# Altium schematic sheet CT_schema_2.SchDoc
size 316 x 185 mm
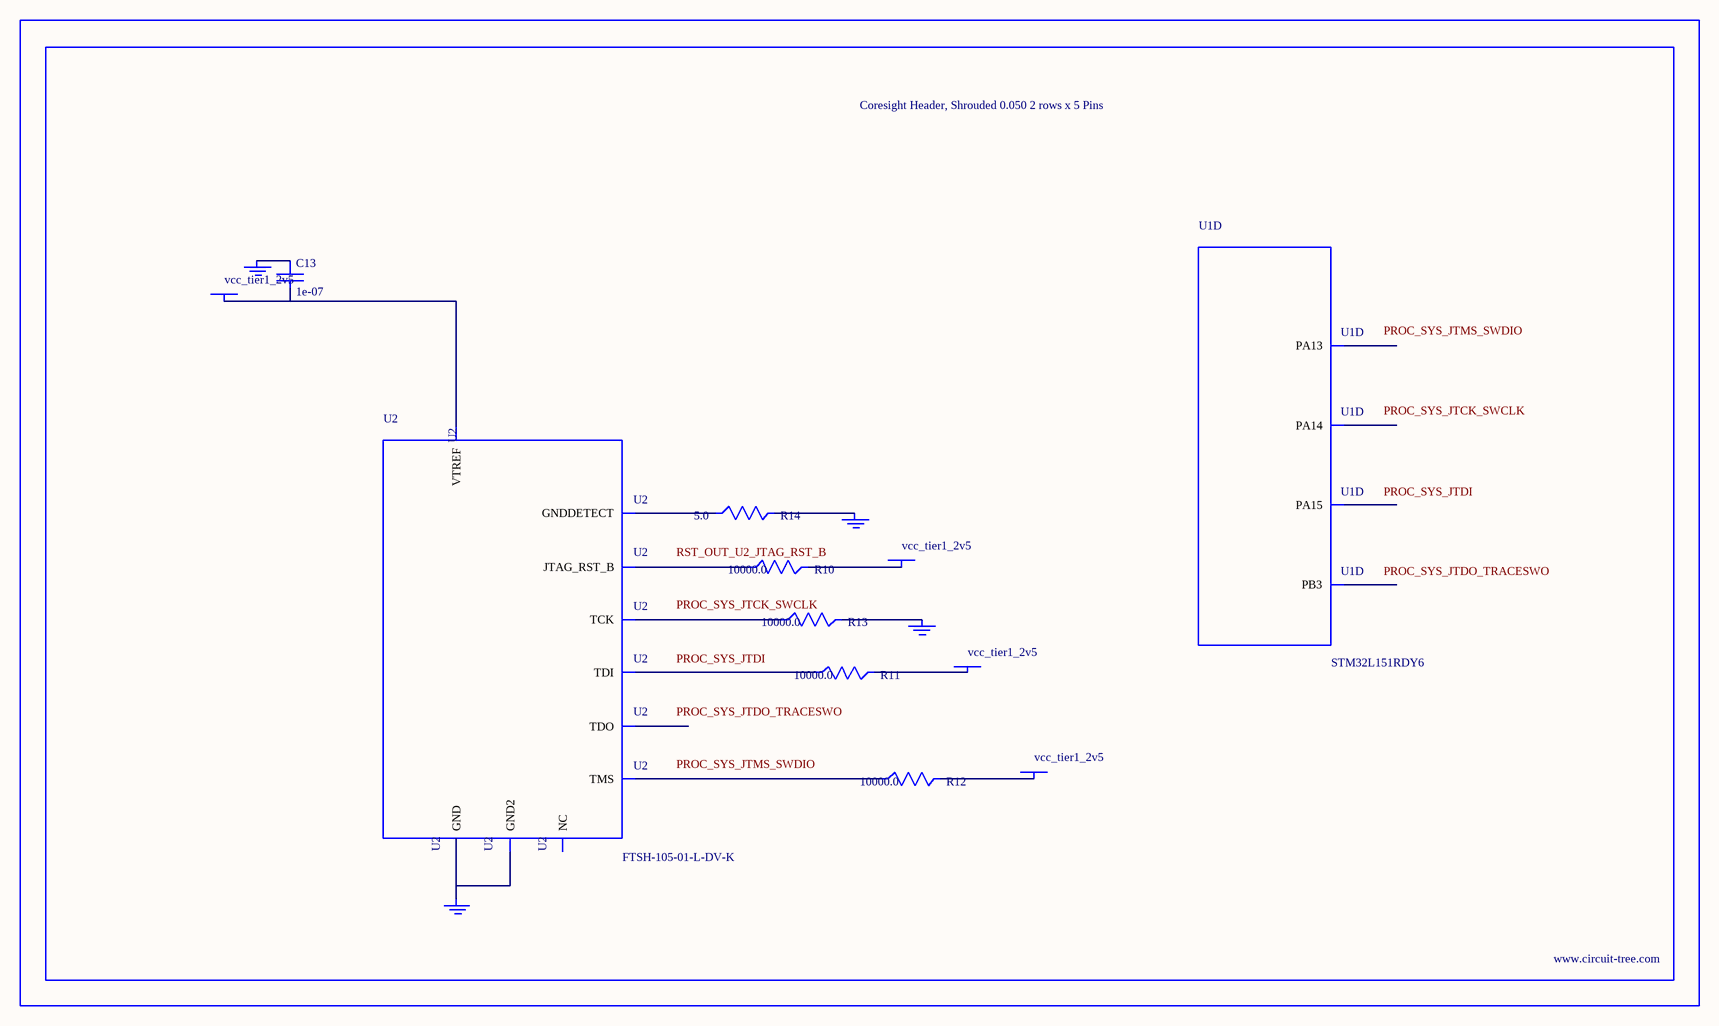
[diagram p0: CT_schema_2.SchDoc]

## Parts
BORDER1  (no value)
C13  1e-07  [C0402]
GND_INSTANCE_1_0  (no value)
GND_INSTANCE_1_1  (no value)
GND_INSTANCE_1_2  (no value)
GND_INSTANCE_1_3  (no value)
POWER_INSTANCE_1_0  vcc_tier1_2v5
POWER_INSTANCE_1_1  vcc_tier1_2v5
POWER_INSTANCE_1_2  vcc_tier1_2v5
POWER_INSTANCE_1_3  vcc_tier1_2v5
R10  10000.0  [R0603]
R11  10000.0  [R0603]
R12  10000.0  [R0603]
R13  10000.0  [R0603]
R14  5.0  [R0603]
U1  STM32L151RDY6  [WLCSP64]  (part D of 8)
U2  FTSH-105-01-L-DV-K  [SAMTEC_FTSH-105-01-L-DV-K]

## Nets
NetC13_1: C13.1 GND_INSTANCE_1_0.0(GND)
NetC13_2: C13.2 POWER_INSTANCE_1_0.0(PWR) U2.1(VTREF)
NetGND_INSTANCE_1_1_0: GND_INSTANCE_1_1.0(GND) R13.2
NetGND_INSTANCE_1_2_0: GND_INSTANCE_1_2.0(GND) R14.2
NetGND_INSTANCE_1_3_0: GND_INSTANCE_1_3.0(GND) U2.3(GND) U2.5(GND2)
NetPOWER_INSTANCE_1_1_0: POWER_INSTANCE_1_1.0(PWR) R12.2
NetPOWER_INSTANCE_1_2_0: POWER_INSTANCE_1_2.0(PWR) R11.2
NetPOWER_INSTANCE_1_3_0: POWER_INSTANCE_1_3.0(PWR) R10.2
NetR10_1: R10.1 U2.10(JTAG_RST_B)
NetR11_1: R11.1 U2.8(TDI)
NetR12_1: R12.1 U2.2(TMS)
NetR13_1: R13.1 U2.4(TCK)
NetR14_1: R14.1 U2.9(GNDDETECT)

Not connected (* = marked no-connect by the designer): U1 A4(PB3) B2(PA14) C3(PA15) D4(PA13); U2 6(TDO) 7(NC)

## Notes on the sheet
- Labels drawn without touching a wire or pin: PROC_SYS_JTCK_SWCLK, PROC_SYS_JTDI, PROC_SYS_JTDO_TRACESWO, PROC_SYS_JTMS_SWDIO, RST_OUT_U2_JTAG_RST_B

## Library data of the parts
BORDER1 = BORDER_PAGE1
C13 = C0402C104K3RACTU
GND_INSTANCE_1_0-GND_INSTANCE_1_3 = GND
POWER_INSTANCE_1_0-POWER_INSTANCE_1_3 = PWR
R10-R13 = RC0603JR-0710KL
R14 = ERJ-3GEYJ5R1V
